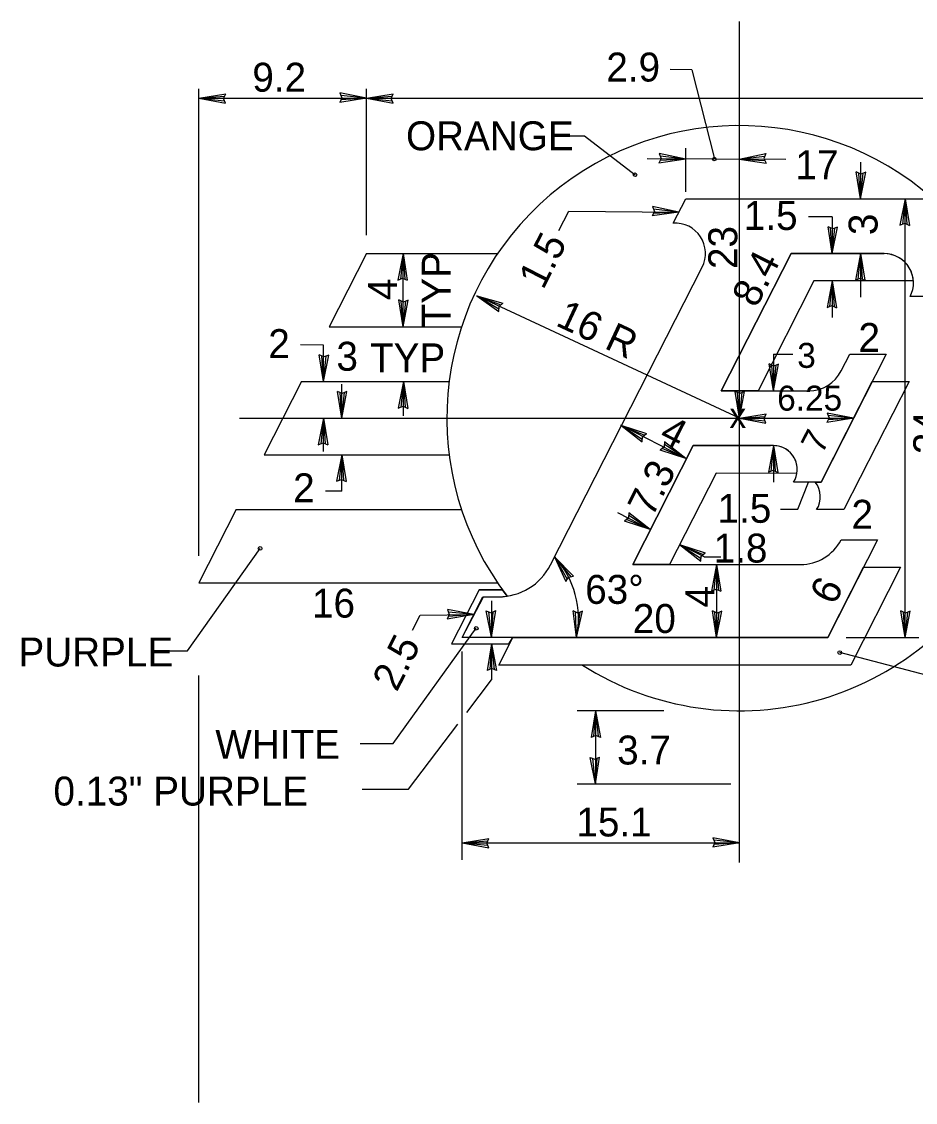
# Model space of a CAD drawing. Extents: x 10268197 to 10269179, y 2141503 to 2142677.
# Drawn here: x 10268669.29 to 10268694.59, y 2142238.37 to 2142268.95 of the extents above; entities that cross this region are included whole.
import ezdxf

# ---------------------------------------------------------------- set-up
doc = ezdxf.new("R2010")
doc.units = 0
for name, color, linetype in [('1', 7, 'Continuous'), ('2', 7, 'Continuous'), ('52', 7, 'Continuous'), ('SOILS_SP83_SHP', 7, 'Continuous')]:
    doc.layers.add(name, color=color, linetype=linetype)

msp = doc.modelspace()

# ---------------------------------------------------------------- linework, layer by layer
at = {"layer": '1'}
for p, q in [((10268689.611, 2142245.155), (10268689.611, 2142268.948)), ((10268688.26, 2142267.586), (10268687.65, 2142267.59)), ((10268688.26, 2142267.586), (10268688.903, 2142265.066)), ((10268674.314, 2142253.83), (10268674.314, 2142267.042)), ((10268679.055, 2142262.902), (10268679.055, 2142267.042)), ((10268674.314, 2142266.783), (10268701.45, 2142266.783)), ((10268684.292, 2142265.718), (10268685.228, 2142265.718)), ((10268685.228, 2142265.718), (10268686.656, 2142264.616)), ((10268688.091, 2142264.136), (10268688.091, 2142265.371)), ((10268690.921, 2142265.042), (10268687, 2142265.069)), ((10268693.04, 2142264.972), (10268693.04, 2142263.937)), ((10268694.302, 2142251.519), (10268694.302, 2142263.937)), ((10268684.503, 2142263.04), (10268684.783, 2142263.589)), ((10268684.783, 2142263.589), (10268687.9, 2142263.561)), ((10268692.24, 2142263.42), (10268691.564, 2142263.42)), ((10268692.24, 2142263.42), (10268692.24, 2142262.385)), ((10268680.09, 2142260.315), (10268680.09, 2142262.385)), ((10268689.095, 2142258.504), (10268691.072, 2142262.385)), ((10268691.072, 2142262.385), (10268693.71, 2142262.385)), ((10268693.04, 2142262.385), (10268693.04, 2142261.155)), ((10268691.722, 2142261.609), (10268690.14, 2142258.504)), ((10268694.537, 2142261.609), (10268691.722, 2142261.609)), ((10268692.24, 2142261.609), (10268692.24, 2142260.574)), ((10268689.611, 2142257.728), (10268682.181, 2142261.193)), ((10268677.838, 2142259.798), (10268677.184, 2142259.802)), ((10268677.838, 2142258.763), (10268677.838, 2142259.798)), ((10268690.576, 2142259.539), (10268690.576, 2142258.504)), ((10268690.576, 2142259.539), (10268691.125, 2142259.539)), ((10268678.356, 2142257.728), (10268678.356, 2142258.692)), ((10268680.102, 2142257.793), (10268680.102, 2142258.763)), ((10268691.922, 2142255.917), (10268693.372, 2142258.763)), ((10268694.417, 2142258.763), (10268692.571, 2142255.141)), ((10268693.372, 2142258.763), (10268694.417, 2142258.763)), ((10268690.14, 2142258.504), (10268689.095, 2142258.504)), ((10268675.463, 2142257.728), (10268692.844, 2142257.728)), ((10268677.838, 2142256.783), (10268677.838, 2142257.728)), ((10268688.098, 2142256.587), (10268686.253, 2142257.527)), ((10268686.591, 2142253.589), (10268688.305, 2142256.952)), ((10268688.305, 2142256.952), (10268690.478, 2142256.945)), ((10268690.576, 2142256.952), (10268690.576, 2142255.917)), ((10268678.356, 2142255.658), (10268678.356, 2142256.693)), ((10268688.954, 2142256.174), (10268687.636, 2142253.589)), ((10268691.238, 2142256.167), (10268688.954, 2142256.174)), ((10268691.268, 2142255.155), (10268691.567, 2142255.917)), ((10268691.759, 2142255.917), (10268691.922, 2142255.917)), ((10268678.356, 2142255.658), (10268677.898, 2142255.662)), ((10268687.087, 2142254.577), (10268686.166, 2142255.046)), ((10268690.772, 2142255.155), (10268691.268, 2142255.155)), ((10268692.571, 2142255.141), (10268691.796, 2142255.141)), ((10268673.989, 2142251.145), (10268676.045, 2142254.044)), ((10268688.609, 2142253.8), (10268687.917, 2142254.153)), ((10268688.609, 2142253.8), (10268689.085, 2142253.8)), ((10268687.636, 2142253.589), (10268686.591, 2142253.589)), ((10268688.965, 2142253.589), (10268688.965, 2142251.519)), ((10268692.113, 2142251.519), (10268693.127, 2142253.509)), ((10268694.173, 2142253.509), (10268692.763, 2142250.743)), ((10268693.127, 2142253.509), (10268694.173, 2142253.509)), ((10268682.593, 2142252.555), (10268682.593, 2142251.527)), ((10268680.356, 2142251.726), (10268680.576, 2142252.157)), ((10268680.576, 2142252.157), (10268682.097, 2142252.171)), ((10268679.815, 2142248.52), (10268682.163, 2142251.782)), ((10268682.593, 2142251.343), (10268682.593, 2142250.322)), ((10268682.8, 2142250.743), (10268683.195, 2142251.519)), ((10268683.195, 2142251.519), (10268692.113, 2142251.519)), ((10268692.631, 2142251.519), (10268694.69, 2142251.519)), ((10268673.272, 2142251.145), (10268673.989, 2142251.145)), ((10268681.765, 2142245.231), (10268681.765, 2142251.122)), ((10268695.11, 2142250.402), (10268692.453, 2142251.097)), ((10268692.763, 2142250.743), (10268682.8, 2142250.743)), ((10268674.298, 2142250.448), (10268674.298, 2142238.369)), ((10268681.891, 2142249.396), (10268682.593, 2142250.322)), ((10268687.468, 2142249.449), (10268685.017, 2142249.449)), ((10268685.534, 2142249.449), (10268685.534, 2142247.379)), ((10268680.248, 2142247.228), (10268681.642, 2142249.068)), ((10268678.879, 2142248.52), (10268679.815, 2142248.52)), ((10268685.017, 2142247.379), (10268689.368, 2142247.379)), ((10268678.934, 2142247.228), (10268680.248, 2142247.228)), ((10268681.765, 2142245.717), (10268689.611, 2142245.717))]:
    msp.add_line(p, q, dxfattribs=at)
msp.add_lwpolyline([(10268682.904, 2142252.873), (10268682.243, 2142252.873), (10268681.465, 2142251.343), (10268683.088, 2142251.343), (10268683.195, 2142251.519), (10268681.765, 2142251.519), (10268682.367, 2142252.671), (10268682.792, 2142252.671), (10268683.04, 2142252.69)], close=True, dxfattribs=at)
for centre in [(10268688.9, 2142265.06), (10268686.656, 2142264.615), (10268676.045, 2142254.043), (10268682.163, 2142251.781), (10268692.453, 2142251.096)]:
    msp.add_circle(centre, 0.0517, dxfattribs=at)
for centre, radius, start, end in [((10268693.71, 2142261.556), 0.828, 3.5833, 90), ((10268690.575, 2142256.278), 0.673, 350.3502, 98.3344), ((10268691.229, 2142255.502), 0.673, 327.421, 37.9799), ((10268682.47, 2142252.055), 2.587, 348.03, 42.5026)]:
    msp.add_arc(centre, radius, start, end, dxfattribs=at)
at = {"layer": '2'}
for p, q in [((10268682.243, 2142252.873), (10268681.465, 2142251.343)), ((10268682.243, 2142252.873), (10268682.904, 2142252.873)), ((10268681.465, 2142251.343), (10268683.088, 2142251.343))]:
    msp.add_line(p, q, dxfattribs=at)
at = {"layer": '52'}
for p, q in [((10268674.314, 2142266.783), (10268675.071, 2142266.903)), ((10268675.01, 2142266.771), (10268675.071, 2142266.903)), ((10268679.055, 2142266.783), (10268678.303, 2142266.929)), ((10268678.303, 2142266.929), (10268678.359, 2142266.795)), ((10268679.055, 2142266.783), (10268679.812, 2142266.903)), ((10268679.751, 2142266.771), (10268679.812, 2142266.903)), ((10268674.314, 2142266.783), (10268675.039, 2142266.834)), ((10268674.314, 2142266.783), (10268675.066, 2142266.637)), ((10268674.314, 2142266.783), (10268675.037, 2142266.707)), ((10268675.066, 2142266.637), (10268675.01, 2142266.771)), ((10268678.359, 2142266.795), (10268678.299, 2142266.663)), ((10268679.055, 2142266.783), (10268678.299, 2142266.663)), ((10268679.055, 2142266.783), (10268678.331, 2142266.732)), ((10268679.055, 2142266.783), (10268678.332, 2142266.859)), ((10268679.055, 2142266.783), (10268679.78, 2142266.834)), ((10268679.055, 2142266.783), (10268679.807, 2142266.637)), ((10268679.055, 2142266.783), (10268679.778, 2142266.707)), ((10268679.807, 2142266.637), (10268679.751, 2142266.771)), ((10268687.393, 2142265.077), (10268687.332, 2142264.945)), ((10268688.09, 2142265.059), (10268687.332, 2142264.945)), ((10268688.09, 2142265.059), (10268687.339, 2142265.212)), ((10268687.339, 2142265.212), (10268687.393, 2142265.077)), ((10268688.09, 2142265.059), (10268687.364, 2142265.014)), ((10268688.09, 2142265.059), (10268687.367, 2142265.141)), ((10268689.607, 2142265.059), (10268690.357, 2142265.212)), ((10268689.607, 2142265.059), (10268690.329, 2142265.141)), ((10268689.607, 2142265.059), (10268690.364, 2142264.945)), ((10268689.607, 2142265.059), (10268690.332, 2142265.014)), ((10268690.357, 2142265.212), (10268690.303, 2142265.077)), ((10268690.303, 2142265.077), (10268690.364, 2142264.945)), ((10268693.04, 2142263.937), (10268692.92, 2142264.694)), ((10268693.051, 2142264.634), (10268692.92, 2142264.694)), ((10268693.04, 2142263.937), (10268692.989, 2142264.662)), ((10268693.04, 2142263.937), (10268693.186, 2142264.689)), ((10268693.04, 2142263.937), (10268693.116, 2142264.66)), ((10268693.186, 2142264.689), (10268693.051, 2142264.634)), ((10268694.302, 2142263.937), (10268694.156, 2142263.185)), ((10268694.302, 2142263.937), (10268694.227, 2142263.215)), ((10268694.302, 2142263.937), (10268694.422, 2142263.181)), ((10268694.302, 2142263.937), (10268694.353, 2142263.213)), ((10268687.204, 2142263.579), (10268687.142, 2142263.448)), ((10268687.9, 2142263.561), (10268687.142, 2142263.448)), ((10268687.9, 2142263.561), (10268687.15, 2142263.713)), ((10268687.15, 2142263.713), (10268687.204, 2142263.579)), ((10268687.9, 2142263.561), (10268687.175, 2142263.517)), ((10268687.9, 2142263.561), (10268687.178, 2142263.642)), ((10268694.156, 2142263.185), (10268694.29, 2142263.241)), ((10268694.29, 2142263.241), (10268694.422, 2142263.181)), ((10268692.24, 2142262.385), (10268692.119, 2142263.141)), ((10268692.251, 2142263.081), (10268692.119, 2142263.141)), ((10268692.24, 2142262.385), (10268692.189, 2142263.109)), ((10268692.24, 2142262.385), (10268692.386, 2142263.136)), ((10268692.24, 2142262.385), (10268692.316, 2142263.107)), ((10268692.386, 2142263.136), (10268692.251, 2142263.081)), ((10268680.09, 2142262.385), (10268679.944, 2142261.633)), ((10268680.09, 2142262.385), (10268680.015, 2142261.662)), ((10268680.09, 2142262.385), (10268680.21, 2142261.628)), ((10268680.09, 2142262.385), (10268680.141, 2142261.66)), ((10268693.04, 2142262.385), (10268692.893, 2142261.633)), ((10268693.04, 2142262.385), (10268692.964, 2142261.662)), ((10268693.04, 2142262.385), (10268693.16, 2142261.628)), ((10268693.04, 2142262.385), (10268693.09, 2142261.66)), ((10268679.944, 2142261.633), (10268680.078, 2142261.688)), ((10268680.078, 2142261.688), (10268680.21, 2142261.628)), ((10268692.893, 2142261.633), (10268693.028, 2142261.688)), ((10268693.028, 2142261.688), (10268693.16, 2142261.628)), ((10268692.24, 2142261.609), (10268692.094, 2142260.857)), ((10268692.24, 2142261.609), (10268692.164, 2142260.886)), ((10268692.24, 2142261.609), (10268692.36, 2142260.852)), ((10268692.24, 2142261.609), (10268692.291, 2142260.885)), ((10268680.09, 2142260.315), (10268679.97, 2142261.072)), ((10268680.102, 2142261.012), (10268679.97, 2142261.072)), ((10268680.09, 2142260.315), (10268680.236, 2142261.067)), ((10268680.236, 2142261.067), (10268680.102, 2142261.012)), ((10268682.181, 2142261.193), (10268682.917, 2142260.981)), ((10268682.181, 2142261.193), (10268682.801, 2142260.743)), ((10268682.181, 2142261.193), (10268682.804, 2142260.819)), ((10268682.181, 2142261.193), (10268682.859, 2142260.932)), ((10268680.09, 2142260.315), (10268680.039, 2142261.04)), ((10268680.09, 2142260.315), (10268680.165, 2142261.038)), ((10268682.801, 2142260.743), (10268682.807, 2142260.888)), ((10268682.807, 2142260.888), (10268682.917, 2142260.981)), ((10268692.094, 2142260.857), (10268692.228, 2142260.912)), ((10268692.228, 2142260.912), (10268692.36, 2142260.852)), ((10268677.838, 2142258.763), (10268677.718, 2142259.519)), ((10268677.85, 2142259.459), (10268677.718, 2142259.519)), ((10268677.838, 2142258.763), (10268677.788, 2142259.487)), ((10268677.838, 2142258.763), (10268677.985, 2142259.514)), ((10268677.838, 2142258.763), (10268677.915, 2142259.485)), ((10268677.985, 2142259.514), (10268677.85, 2142259.459)), ((10268690.576, 2142258.504), (10268690.456, 2142259.261)), ((10268690.588, 2142259.201), (10268690.456, 2142259.261)), ((10268690.576, 2142258.504), (10268690.721, 2142259.256)), ((10268690.721, 2142259.256), (10268690.588, 2142259.201)), ((10268690.576, 2142258.504), (10268690.525, 2142259.229)), ((10268690.576, 2142258.504), (10268690.651, 2142259.227)), ((10268680.102, 2142258.763), (10268679.956, 2142258.011)), ((10268680.102, 2142258.763), (10268680.027, 2142258.04)), ((10268680.102, 2142258.763), (10268680.222, 2142258.006)), ((10268680.102, 2142258.763), (10268680.153, 2142258.038)), ((10268678.356, 2142257.728), (10268678.236, 2142258.484)), ((10268678.368, 2142258.425), (10268678.236, 2142258.484)), ((10268678.356, 2142257.728), (10268678.306, 2142258.452)), ((10268678.356, 2142257.728), (10268678.502, 2142258.48)), ((10268678.356, 2142257.728), (10268678.432, 2142258.451)), ((10268678.502, 2142258.48), (10268678.368, 2142258.425)), ((10268689.611, 2142257.728), (10268689.491, 2142258.484)), ((10268689.622, 2142258.425), (10268689.491, 2142258.484)), ((10268689.611, 2142257.728), (10268689.56, 2142258.452)), ((10268689.611, 2142257.728), (10268689.757, 2142258.48)), ((10268689.611, 2142257.728), (10268689.686, 2142258.451)), ((10268689.757, 2142258.48), (10268689.622, 2142258.425)), ((10268679.956, 2142258.011), (10268680.09, 2142258.066)), ((10268680.09, 2142258.066), (10268680.222, 2142258.006)), ((10268677.838, 2142257.728), (10268677.692, 2142256.976)), ((10268677.838, 2142257.728), (10268677.763, 2142257.005)), ((10268677.838, 2142257.728), (10268677.959, 2142256.971)), ((10268677.838, 2142257.728), (10268677.889, 2142257.004)), ((10268689.611, 2142257.728), (10268690.367, 2142257.848)), ((10268689.611, 2142257.728), (10268690.335, 2142257.779)), ((10268689.611, 2142257.728), (10268690.363, 2142257.582)), ((10268689.611, 2142257.728), (10268690.334, 2142257.652)), ((10268690.307, 2142257.716), (10268690.367, 2142257.848)), ((10268690.363, 2142257.582), (10268690.307, 2142257.716)), ((10268692.148, 2142257.74), (10268692.088, 2142257.608)), ((10268692.844, 2142257.728), (10268692.088, 2142257.608)), ((10268692.844, 2142257.728), (10268692.093, 2142257.874)), ((10268692.093, 2142257.874), (10268692.148, 2142257.74)), ((10268692.844, 2142257.728), (10268692.12, 2142257.677)), ((10268692.844, 2142257.728), (10268692.122, 2142257.804)), ((10268686.253, 2142257.527), (10268686.983, 2142257.29)), ((10268686.253, 2142257.527), (10268686.857, 2142257.056)), ((10268686.253, 2142257.527), (10268686.863, 2142257.132)), ((10268686.253, 2142257.527), (10268686.922, 2142257.243)), ((10268686.857, 2142257.056), (10268686.869, 2142257.2)), ((10268686.869, 2142257.2), (10268686.983, 2142257.29)), ((10268677.692, 2142256.976), (10268677.827, 2142257.031)), ((10268677.827, 2142257.031), (10268677.959, 2142256.971)), ((10268687.483, 2142256.914), (10268687.369, 2142256.823)), ((10268688.098, 2142256.587), (10268687.369, 2142256.823)), ((10268688.098, 2142256.587), (10268687.429, 2142256.871)), ((10268687.495, 2142257.059), (10268687.483, 2142256.914)), ((10268688.098, 2142256.587), (10268687.489, 2142256.983)), ((10268688.098, 2142256.587), (10268687.495, 2142257.059)), ((10268690.576, 2142256.952), (10268690.43, 2142256.2)), ((10268690.576, 2142256.952), (10268690.501, 2142256.229)), ((10268690.576, 2142256.952), (10268690.696, 2142256.195)), ((10268690.576, 2142256.952), (10268690.626, 2142256.228)), ((10268678.356, 2142256.693), (10268678.21, 2142255.941)), ((10268678.356, 2142256.693), (10268678.28, 2142255.971)), ((10268678.356, 2142256.693), (10268678.476, 2142255.937)), ((10268678.356, 2142256.693), (10268678.407, 2142255.969)), ((10268690.43, 2142256.2), (10268690.564, 2142256.255)), ((10268690.564, 2142256.255), (10268690.696, 2142256.195)), ((10268678.21, 2142255.941), (10268678.344, 2142255.997)), ((10268678.344, 2142255.997), (10268678.476, 2142255.937)), ((10268686.484, 2142255.048), (10268686.472, 2142254.904)), ((10268687.087, 2142254.577), (10268686.478, 2142254.972)), ((10268687.087, 2142254.577), (10268686.484, 2142255.048)), ((10268686.472, 2142254.904), (10268686.359, 2142254.813)), ((10268687.087, 2142254.577), (10268686.359, 2142254.813)), ((10268687.087, 2142254.577), (10268686.419, 2142254.861)), ((10268687.917, 2142254.153), (10268688.646, 2142253.917)), ((10268687.917, 2142254.153), (10268688.521, 2142253.682)), ((10268687.917, 2142254.153), (10268688.527, 2142253.758)), ((10268687.917, 2142254.153), (10268688.586, 2142253.869)), ((10268684.377, 2142253.803), (10268684.914, 2142253.257)), ((10268684.377, 2142253.803), (10268684.696, 2142253.106)), ((10268684.377, 2142253.803), (10268684.736, 2142253.172)), ((10268684.377, 2142253.803), (10268684.84, 2142253.243)), ((10268688.521, 2142253.682), (10268688.533, 2142253.826)), ((10268688.533, 2142253.826), (10268688.646, 2142253.917)), ((10268688.965, 2142253.589), (10268688.819, 2142252.837)), ((10268688.965, 2142253.589), (10268688.89, 2142252.866)), ((10268688.965, 2142253.589), (10268689.085, 2142252.832)), ((10268688.965, 2142253.589), (10268689.015, 2142252.864)), ((10268684.696, 2142253.106), (10268684.772, 2142253.23)), ((10268684.772, 2142253.23), (10268684.914, 2142253.257)), ((10268688.819, 2142252.837), (10268688.953, 2142252.892)), ((10268688.953, 2142252.892), (10268689.085, 2142252.832)), ((10268682.097, 2142252.171), (10268681.344, 2142252.31)), ((10268681.344, 2142252.31), (10268681.4, 2142252.176)), ((10268682.097, 2142252.171), (10268681.373, 2142252.24)), ((10268682.593, 2142251.527), (10268682.446, 2142252.278)), ((10268682.446, 2142252.278), (10268682.581, 2142252.223)), ((10268682.593, 2142251.527), (10268682.517, 2142252.249)), ((10268682.581, 2142252.223), (10268682.712, 2142252.283)), ((10268682.593, 2142251.527), (10268682.712, 2142252.283)), ((10268682.593, 2142251.527), (10268682.643, 2142252.251)), ((10268685.001, 2142251.519), (10268684.907, 2142252.279)), ((10268685.038, 2142252.214), (10268684.907, 2142252.279)), ((10268685.001, 2142251.519), (10268684.976, 2142252.245)), ((10268685.001, 2142251.519), (10268685.173, 2142252.265)), ((10268685.001, 2142251.519), (10268685.101, 2142252.238)), ((10268685.173, 2142252.265), (10268685.038, 2142252.214)), ((10268688.965, 2142251.519), (10268688.845, 2142252.275)), ((10268688.977, 2142252.215), (10268688.845, 2142252.275)), ((10268688.965, 2142251.519), (10268688.914, 2142252.243)), ((10268688.965, 2142251.519), (10268689.111, 2142252.27)), ((10268688.965, 2142251.519), (10268689.041, 2142252.241)), ((10268689.111, 2142252.27), (10268688.977, 2142252.215)), ((10268694.302, 2142251.519), (10268694.182, 2142252.275)), ((10268694.314, 2142252.215), (10268694.182, 2142252.275)), ((10268694.302, 2142251.519), (10268694.251, 2142252.243)), ((10268694.302, 2142251.519), (10268694.448, 2142252.27)), ((10268694.302, 2142251.519), (10268694.377, 2142252.241)), ((10268694.448, 2142252.27), (10268694.314, 2142252.215)), ((10268681.4, 2142252.176), (10268681.341, 2142252.044)), ((10268682.097, 2142252.171), (10268681.341, 2142252.044)), ((10268682.097, 2142252.171), (10268681.373, 2142252.114)), ((10268682.593, 2142251.343), (10268682.472, 2142250.587)), ((10268682.593, 2142251.343), (10268682.542, 2142250.619)), ((10268682.593, 2142251.343), (10268682.738, 2142250.591)), ((10268682.593, 2142251.343), (10268682.668, 2142250.619)), ((10268682.604, 2142250.646), (10268682.472, 2142250.587)), ((10268682.738, 2142250.591), (10268682.604, 2142250.646)), ((10268685.534, 2142249.449), (10268685.414, 2142248.693)), ((10268685.534, 2142249.449), (10268685.483, 2142248.725)), ((10268685.534, 2142249.449), (10268685.68, 2142248.697)), ((10268685.534, 2142249.449), (10268685.609, 2142248.726)), ((10268685.545, 2142248.752), (10268685.414, 2142248.693)), ((10268685.68, 2142248.697), (10268685.545, 2142248.752)), ((10268685.534, 2142247.379), (10268685.388, 2142248.131)), ((10268685.388, 2142248.131), (10268685.522, 2142248.076)), ((10268685.534, 2142247.379), (10268685.458, 2142248.102)), ((10268685.522, 2142248.076), (10268685.654, 2142248.136)), ((10268685.534, 2142247.379), (10268685.654, 2142248.136)), ((10268685.534, 2142247.379), (10268685.585, 2142248.104)), ((10268681.765, 2142245.717), (10268682.521, 2142245.838)), ((10268682.461, 2142245.706), (10268682.521, 2142245.838)), ((10268689.611, 2142245.717), (10268688.857, 2142245.857)), ((10268688.857, 2142245.857), (10268688.914, 2142245.724)), ((10268689.611, 2142245.717), (10268688.888, 2142245.787)), ((10268681.765, 2142245.717), (10268682.489, 2142245.769)), ((10268681.765, 2142245.717), (10268682.516, 2142245.572)), ((10268681.765, 2142245.717), (10268682.487, 2142245.642)), ((10268682.516, 2142245.572), (10268682.461, 2142245.706)), ((10268688.914, 2142245.724), (10268688.856, 2142245.591)), ((10268689.611, 2142245.717), (10268688.856, 2142245.591)), ((10268689.611, 2142245.717), (10268688.887, 2142245.661))]:
    msp.add_line(p, q, dxfattribs=at)
at = {"layer": 'SOILS_SP83_SHP'}
for p, q in [((10268687.739, 2142263.243), (10268688.091, 2142263.937)), ((10268688.091, 2142263.937), (10268696.888, 2142263.937)), ((10268679.055, 2142262.385), (10268678.002, 2142260.315)), ((10268679.055, 2142262.385), (10268682.766, 2142262.385)), ((10268691.072, 2142262.385), (10268689.095, 2142258.504)), ((10268689.095, 2142258.504), (10268691.072, 2142262.385)), ((10268693.71, 2142262.385), (10268691.072, 2142262.385)), ((10268691.072, 2142262.385), (10268693.71, 2142262.385)), ((10268684.262, 2142253.575), (10268688.556, 2142262.004)), ((10268691.722, 2142261.609), (10268690.14, 2142258.504)), ((10268694.537, 2142261.609), (10268691.722, 2142261.609)), ((10268695.479, 2142261.171), (10268694.443, 2142261.171)), ((10268678.002, 2142260.315), (10268681.747, 2142260.315)), ((10268693.767, 2142259.539), (10268691.922, 2142255.917)), ((10268692.493, 2142259.069), (10268692.732, 2142259.539)), ((10268692.732, 2142259.539), (10268693.767, 2142259.539)), ((10268677.212, 2142258.763), (10268676.158, 2142256.693)), ((10268677.212, 2142258.763), (10268681.396, 2142258.763)), ((10268691.922, 2142255.917), (10268693.372, 2142258.763)), ((10268694.417, 2142258.763), (10268692.571, 2142255.141)), ((10268693.372, 2142258.763), (10268694.417, 2142258.763)), ((10268689.095, 2142258.504), (10268691.571, 2142258.504)), ((10268690.14, 2142258.504), (10268689.095, 2142258.504)), ((10268688.305, 2142256.952), (10268686.591, 2142253.589)), ((10268686.591, 2142253.589), (10268688.305, 2142256.952)), ((10268690.576, 2142256.952), (10268688.305, 2142256.952)), ((10268688.305, 2142256.952), (10268690.478, 2142256.945)), ((10268676.158, 2142256.693), (10268681.396, 2142256.693)), ((10268688.954, 2142256.174), (10268687.636, 2142253.589)), ((10268691.238, 2142256.167), (10268688.954, 2142256.174)), ((10268691.922, 2142255.917), (10268691.143, 2142255.917)), ((10268691.759, 2142255.917), (10268691.922, 2142255.917)), ((10268675.368, 2142255.141), (10268674.314, 2142253.071)), ((10268675.368, 2142255.141), (10268681.747, 2142255.141)), ((10268692.571, 2142255.141), (10268691.796, 2142255.141)), ((10268693.523, 2142254.285), (10268692.113, 2142251.519)), ((10268692.487, 2142254.285), (10268693.523, 2142254.285)), ((10268686.591, 2142253.589), (10268691.34, 2142253.589)), ((10268687.636, 2142253.589), (10268686.591, 2142253.589)), ((10268692.113, 2142251.519), (10268693.127, 2142253.509)), ((10268694.173, 2142253.509), (10268692.763, 2142250.743)), ((10268693.127, 2142253.509), (10268694.173, 2142253.509)), ((10268674.314, 2142253.071), (10268682.766, 2142253.071)), ((10268681.765, 2142251.519), (10268682.352, 2142252.671)), ((10268682.352, 2142252.671), (10268682.786, 2142252.671)), ((10268692.113, 2142251.519), (10268681.765, 2142251.519)), ((10268682.8, 2142250.743), (10268683.195, 2142251.519)), ((10268683.195, 2142251.519), (10268692.113, 2142251.519)), ((10268692.763, 2142250.743), (10268682.8, 2142250.743))]:
    msp.add_line(p, q, dxfattribs=at)
for centre, radius, start, end in [((10268689.611, 2142257.727), 8.279, 48.5904, 217.4727), ((10268687.795, 2142262.391), 0.854, 332.9998, 93.8045), ((10268693.71, 2142261.556), 0.828, 332.2089, 90), ((10268693.71, 2142261.556), 0.828, 3.5833, 90), ((10268691.571, 2142259.538), 1.035, 270, 332.9883), ((10268690.575, 2142256.278), 0.673, 350.3502, 98.3344), ((10268690.575, 2142256.278), 0.673, 327.421, 90), ((10268691.229, 2142255.502), 0.673, 327.421, 37.9799), ((10268689.611, 2142257.727), 8.279, 237.5383, 335.047), ((10268691.34, 2142254.881), 1.294, 270, 332.5096), ((10268682.786, 2142254.327), 1.656, 270, 332.9991)]:
    msp.add_arc(centre, radius, start, end, dxfattribs=at)

# ---------------------------------------------------------------- texts
at = {"layer": '1'}
for s, height, p in [('9.2', 0.8187, (10268675.824, 2142266.965)), ('2.9', 0.8187, (10268685.844, 2142267.253)), ('ORANGE', 0.8187, (10268680.174, 2142265.308)), ('17', 0.8187, (10268691.197, 2142264.49)), ('1.5', 0.8187, (10268689.736, 2142263.053)), ('2', 0.819, (10268676.276, 2142259.427)), ('2', 0.819, (10268692.981, 2142259.601)), ('3', 0.819, (10268678.204, 2142259.07)), ('TYP', 0.8187, (10268679.154, 2142259.025)), ('3', 0.706, (10268691.248, 2142259.151)), ('6.25', 0.706, (10268690.68, 2142257.941)), ('x', 0.706, (10268689.33, 2142257.452)), ('2', 0.819, (10268676.98, 2142255.348)), ('1.5', 0.8187, (10268688.992, 2142254.768)), ('2', 0.819, (10268692.783, 2142254.598)), ('1.8', 0.8187, (10268688.882, 2142253.642)), ('63°', 0.8187, (10268685.246, 2142252.474)), ('16', 0.8187, (10268677.512, 2142252.085)), ('20', 0.8187, (10268686.594, 2142251.65)), ('PURPLE', 0.8187, (10268669.204, 2142250.702)), ('WHITE', 0.8187, (10268674.775, 2142248.09)), ('3.7', 0.8187, (10268686.15, 2142247.929)), ('0.13" PURPLE', 0.81867, (10268670.196, 2142246.768)), ('15.1', 0.8187, (10268684.997, 2142245.893))]:
    msp.add_text(s, height=height, dxfattribs=at).set_placement(p)
for s, height, rotation, p in [('3', 0.819, 90, (10268693.521, 2142262.907)), ('1.5', 0.8187, 63, (10268684.056, 2142261.34)), ('23', 0.8187, 90, (10268689.55, 2142261.947)), ('TYP', 0.8187, 90, (10268681.438, 2142260.297)), ('8.4', 0.8187, 63, (10268690.09, 2142260.821)), ('4', 0.819, 90, (10268679.92, 2142261.069)), ('16 R', 0.8187, 334.9991, (10268684.38, 2142260.363)), ('24', 0.8187, 90, (10268695.351, 2142256.708)), ('4', 0.819, 332.9866, (10268687.302, 2142257.105)), ('7', 0.706, 63, (10268691.95, 2142256.686)), ('7.3', 0.8187, 63, (10268687.142, 2142254.899)), ('6', 0.819, 63, (10268692.297, 2142252.406)), ('4', 0.819, 90, (10268688.902, 2142252.37)), ('2.5', 0.8187, 63, (10268679.913, 2142249.959))]:
    msp.add_text(s, height=height, rotation=rotation, dxfattribs=at).set_placement(p)

doc.saveas('drawing.dxf')
